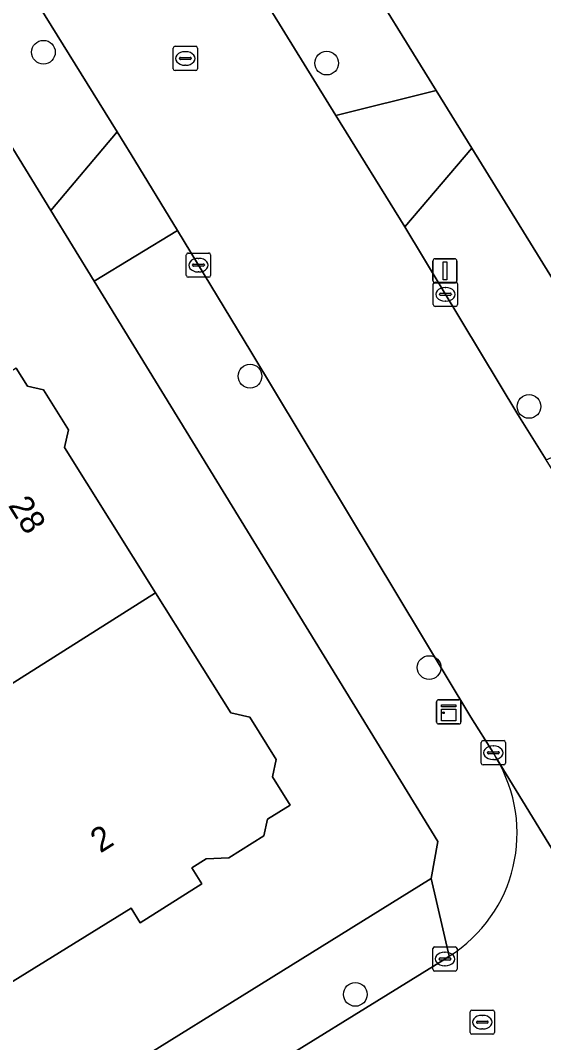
# Model space of a CAD drawing. Extents: x 161347 to 161881, y 382161 to 382804.
# Drawn here: x 161600.22 to 161621.78, y 382389.57 to 382431.67 of the extents above; entities that cross this region are included whole.
import ezdxf

# ---------------------------------------------------------------- set-up
doc = ezdxf.new("R2010")
doc.units = 0
for name, color, linetype in [('IMGEO_Boom', 7, 'Continuous'), ('IMGEO_Erf', 7, 'Continuous'), ('IMGEO_Kast', 7, 'Continuous'), ('IMGEO_Kolk', 7, 'Continuous'), ('IMGEO_Lichtmast', 7, 'Continuous'), ('IMGEO_Pand', 7, 'Continuous'), ('IMGEO_Pand_nummerreeks', 7, 'Continuous'), ('IMGEO_Rijbaan_lokaal_gesloten', 7, 'Continuous'), ('IMGEO_Rijbaan_lokaal_open', 7, 'Continuous'), ('IMGEO_Rioolput', 7, 'Continuous'), ('IMGEO_Voetpad_open', 7, 'Continuous')]:
    doc.layers.add(name, color=color, linetype=linetype)

msp = doc.modelspace()

# ---------------------------------------------------------------- linework, layer by layer
at = {"layer": 'IMGEO_Boom'}
for centre in [(161601.169, 382430.36), (161612.84, 382429.913), (161609.683, 382417.02), (161621.177, 382415.774), (161617.061, 382405.019), (161614.021, 382391.559)]:
    msp.add_circle(centre, 0.489, dxfattribs=at)
at = {"layer": 'IMGEO_Erf'}
for points in [[(161596.873, 382461.934), (161606.595, 382446.199), (161610.46, 382439.943), (161617.351, 382428.79), (161618.821, 382426.407), (161625.713, 382415.253), (161627.403, 382412.518), (161635.49, 382399.431), (161637.176, 382396.702), (161644.13, 382385.439), (161645.645, 382382.995), (161648.386, 382378.558), (161650.079, 382375.819), (161660.585, 382358.814), (161662.853, 382355.14), (161668.204, 382346.482), (161670.894, 382342.449), (161673.167, 382339.282), (161675.39, 382336.184)], [(161617.144, 382396.335), (161617.418, 382397.853), (161603.267, 382420.926), (161601.482, 382423.837), (161585.851, 382449.323), (161572.419, 382451.387), (161564.764, 382446.042), (161558.459, 382441.915), (161500, 382404.037), (161487.478, 382395.924)], [(161600.042, 382417.352), (161600.512, 382416.603), (161601.175, 382416.451), (161602.206, 382414.804), (161602.041, 382414.084), (161605.788, 382408.1), (161608.887, 382403.152), (161609.674, 382402.97), (161610.764, 382401.23), (161610.602, 382400.523), (161611.333, 382399.354), (161610.406, 382398.773), (161610.248, 382398.086), (161608.803, 382397.181), (161607.874, 382397.148), (161607.282, 382396.777), (161607.703, 382396.106), (161605.156, 382394.512), (161604.784, 382395.105), (161598.864, 382391.464)], [(161492.761, 382318.284), (161495.67, 382317.265), (161500, 382320.746), (161506.91, 382326.302), (161519.365, 382335.787), (161532.97, 382344.41), (161567.929, 382365.979), (161578.374, 382372.283), (161617.144, 382396.335)]]:
    msp.add_lwpolyline(points, dxfattribs=at)
at = {"layer": 'IMGEO_Kast'}
for p, q in [((161617.37, 382402.77), (161617.37, 382403.611)), ((161617.37, 382403.611), (161617.37, 382402.77)), ((161617.445, 382403.695), (161618.286, 382403.695)), ((161618.286, 382403.695), (161617.445, 382403.695)), ((161618.37, 382403.62), (161618.37, 382402.779)), ((161618.37, 382402.779), (161618.37, 382403.62)), ((161618.295, 382402.695), (161617.454, 382402.695)), ((161617.454, 382402.695), (161618.295, 382402.695))]:
    msp.add_line(p, q, dxfattribs=at)
for points in [[(161617.565, 382403.485), (161618.165, 382403.485), (161618.165, 382403.4), (161617.565, 382403.4), (161617.565, 382403.485)], [(161617.565, 382403.31), (161618.165, 382403.31), (161618.165, 382402.821), (161617.565, 382402.821), (161617.565, 382403.31)]]:
    msp.add_lwpolyline(points, dxfattribs=at)
msp.add_circle((161617.649, 382403.159), 0.0377, dxfattribs=at)
for centre, start, end in [((161617.448, 382403.617), 92.4484, 184.2845), ((161617.448, 382403.617), 92.4484, 184.2845), ((161618.292, 382403.617), 2.4484, 94.2845), ((161618.292, 382403.617), 2.4484, 94.2845), ((161617.448, 382402.773), 182.4484, 274.2845), ((161617.448, 382402.773), 182.4484, 274.2845), ((161618.292, 382402.773), 272.4484, 4.2845), ((161618.292, 382402.773), 272.4484, 4.2845)]:
    msp.add_arc(centre, 0.0779, start, end, dxfattribs=at)
at = {"layer": 'IMGEO_Kolk'}
for p, q in [((161607.133, 382422.092), (161607.985, 382422.092)), ((161607.058, 382421.166), (161607.058, 382422.018)), ((161607.546, 382421.872), (161607.571, 382421.872)), ((161608.059, 382422.018), (161608.059, 382421.166)), ((161607.317, 382421.586), (161607.317, 382421.598)), ((161607.755, 382421.549), (161607.357, 382421.549)), ((161607.36, 382421.635), (161607.758, 382421.635)), ((161607.569, 382421.312), (161607.544, 382421.312)), ((161607.801, 382421.598), (161607.801, 382421.586)), ((161607.985, 382421.092), (161607.133, 382421.092)), ((161617.234, 382419.965), (161617.234, 382420.817)), ((161617.309, 382420.891), (161618.161, 382420.891)), ((161618.235, 382420.817), (161618.235, 382419.965)), ((161617.493, 382420.385), (161617.493, 382420.397)), ((161617.536, 382420.434), (161617.934, 382420.434)), ((161617.722, 382420.671), (161617.747, 382420.671)), ((161617.977, 382420.397), (161617.977, 382420.385)), ((161617.931, 382420.348), (161617.533, 382420.348)), ((161617.745, 382420.111), (161617.72, 382420.111)), ((161618.161, 382419.891), (161617.309, 382419.891)), ((161619.207, 382401.083), (161619.207, 382401.935)), ((161619.282, 382402.009), (161620.134, 382402.009)), ((161620.208, 382401.935), (161620.208, 382401.083)), ((161619.466, 382401.503), (161619.466, 382401.515)), ((161619.904, 382401.466), (161619.506, 382401.466)), ((161619.509, 382401.552), (161619.907, 382401.552)), ((161619.695, 382401.789), (161619.72, 382401.789)), ((161619.95, 382401.515), (161619.95, 382401.503)), ((161619.718, 382401.229), (161619.693, 382401.229)), ((161620.134, 382401.009), (161619.282, 382401.009)), ((161617.213, 382392.591), (161617.213, 382393.443)), ((161617.288, 382393.517), (161618.14, 382393.517)), ((161618.214, 382393.443), (161618.214, 382392.591)), ((161617.472, 382393.011), (161617.472, 382393.023)), ((161617.515, 382393.06), (161617.913, 382393.06)), ((161617.701, 382393.297), (161617.726, 382393.297)), ((161617.956, 382393.023), (161617.956, 382393.011)), ((161617.91, 382392.974), (161617.512, 382392.974)), ((161617.724, 382392.737), (161617.699, 382392.737)), ((161618.14, 382392.517), (161617.288, 382392.517))]:
    msp.add_line(p, q, dxfattribs=at)
for points in [[(161607.133, 382422.092), (161607.985, 382422.092)], [(161607.058, 382421.166), (161607.058, 382422.018)], [(161608.059, 382422.018), (161608.059, 382421.166)], [(161607.985, 382421.092), (161607.133, 382421.092)], [(161617.234, 382419.965), (161617.234, 382420.817)], [(161617.309, 382420.891), (161618.161, 382420.891)], [(161618.235, 382420.817), (161618.235, 382419.965)], [(161618.161, 382419.891), (161617.309, 382419.891)], [(161619.207, 382401.083), (161619.207, 382401.935)], [(161619.282, 382402.009), (161620.134, 382402.009)], [(161620.208, 382401.935), (161620.208, 382401.083)], [(161620.134, 382401.009), (161619.282, 382401.009)], [(161617.213, 382392.591), (161617.213, 382393.443)], [(161617.288, 382393.517), (161618.14, 382393.517)], [(161618.214, 382393.443), (161618.214, 382392.591)], [(161618.14, 382392.517), (161617.288, 382392.517)]]:
    msp.add_lwpolyline(points, dxfattribs=at)
for centre, radius, start, end in [((161607.135, 382422.016), 0.0765, 91.552, 178.448), ((161607.135, 382422.016), 0.0765, 91.552, 178.448), ((161607.983, 382422.016), 0.0765, 1.552, 88.448), ((161607.983, 382422.016), 0.0765, 1.552, 88.448), ((161607.357, 382421.595), 0.0403, 85.8775, 175.7526), ((161607.354, 382421.585), 0.0366, 178.938, 274.7102), ((161607.758, 382421.592), 0.043, 264.8664, 352.4533), ((161607.762, 382421.597), 0.0386, 1.7309, 96.639), ((161607.135, 382421.168), 0.0765, 181.552, 268.448), ((161607.135, 382421.168), 0.0765, 181.552, 268.448), ((161607.983, 382421.168), 0.0765, 271.552, 358.448), ((161607.983, 382421.168), 0.0765, 271.552, 358.448), ((161617.311, 382420.815), 0.0765, 91.552, 178.448), ((161617.311, 382420.815), 0.0765, 91.552, 178.448), ((161618.159, 382420.815), 0.0765, 1.552, 88.448), ((161618.159, 382420.815), 0.0765, 1.552, 88.448), ((161617.533, 382420.394), 0.0403, 85.8775, 175.7526), ((161617.53, 382420.384), 0.0366, 178.938, 274.7102), ((161617.934, 382420.391), 0.043, 264.8664, 352.4533), ((161617.938, 382420.396), 0.0386, 1.7309, 96.639), ((161617.311, 382419.967), 0.0765, 181.552, 268.448), ((161617.311, 382419.967), 0.0765, 181.552, 268.448), ((161618.159, 382419.967), 0.0765, 271.552, 358.448), ((161618.159, 382419.967), 0.0765, 271.552, 358.448), ((161619.284, 382401.933), 0.0765, 91.552, 178.448), ((161619.284, 382401.933), 0.0765, 91.552, 178.448), ((161620.132, 382401.933), 0.0765, 1.552, 88.448), ((161620.132, 382401.933), 0.0765, 1.552, 88.448), ((161619.506, 382401.512), 0.0403, 85.8775, 175.7526), ((161619.503, 382401.502), 0.0366, 178.938, 274.7102), ((161619.907, 382401.509), 0.043, 264.8664, 352.4533), ((161619.911, 382401.514), 0.0386, 1.7309, 96.639), ((161619.284, 382401.085), 0.0765, 181.552, 268.448), ((161619.284, 382401.085), 0.0765, 181.552, 268.448), ((161620.132, 382401.085), 0.0765, 271.552, 358.448), ((161620.132, 382401.085), 0.0765, 271.552, 358.448), ((161617.29, 382393.441), 0.0765, 91.552, 178.448), ((161617.29, 382393.441), 0.0765, 91.552, 178.448), ((161618.138, 382393.441), 0.0765, 1.552, 88.448), ((161618.138, 382393.441), 0.0765, 1.552, 88.448), ((161617.512, 382393.02), 0.0403, 85.8775, 175.7526), ((161617.917, 382393.022), 0.0386, 1.7309, 96.639), ((161617.509, 382393.01), 0.0366, 178.938, 274.7102), ((161617.913, 382393.017), 0.043, 264.8664, 352.4533), ((161617.29, 382392.593), 0.0765, 181.552, 268.448), ((161617.29, 382392.593), 0.0765, 181.552, 268.448), ((161618.138, 382392.593), 0.0765, 271.552, 358.448), ((161618.138, 382392.593), 0.0765, 271.552, 358.448)]:
    msp.add_arc(centre, radius, start, end, dxfattribs=at)
for centre, major_axis, ratio, start_param, end_param in [((161607.545, 382421.592), (-0.387, 0.002), 0.722429, 4.712389, 7.853982), ((161607.57, 382421.592), (-0.39, 0.002), 0.717154, 1.570796, 4.712389), ((161617.721, 382420.391), (-0.387, 0.002), 0.722429, 4.712389, 7.853982), ((161617.746, 382420.391), (-0.39, 0.002), 0.717154, 1.570796, 4.712389), ((161619.694, 382401.509), (-0.387, 0.002), 0.722429, 4.712389, 7.853982), ((161619.719, 382401.509), (-0.39, 0.002), 0.717154, 1.570796, 4.712389), ((161617.7, 382393.017), (-0.387, 0.002), 0.722429, 4.712389, 7.853982), ((161617.725, 382393.017), (-0.39, 0.002), 0.717154, 1.570796, 4.712389)]:
    msp.add_ellipse(centre, major_axis=major_axis, ratio=ratio, start_param=start_param, end_param=end_param, dxfattribs=at)
at = {"layer": 'IMGEO_Lichtmast'}
for p, q in [((161617.216, 382420.958), (161617.216, 382421.758)), ((161617.216, 382421.758), (161617.216, 382420.958)), ((161617.316, 382421.858), (161618.106, 382421.858)), ((161618.106, 382421.858), (161617.316, 382421.858)), ((161618.206, 382421.758), (161618.206, 382420.958)), ((161618.206, 382420.958), (161618.206, 382421.758)), ((161618.106, 382420.858), (161617.316, 382420.858)), ((161617.316, 382420.858), (161618.106, 382420.858))]:
    msp.add_line(p, q, dxfattribs=at)
msp.add_lwpolyline([(161617.636, 382421.733), (161617.786, 382421.733), (161617.786, 382420.983), (161617.636, 382420.983), (161617.636, 382421.733)], dxfattribs=at)
for centre, start, end in [((161617.316, 382421.758), 90, 180), ((161617.316, 382421.758), 90, 180), ((161618.106, 382421.758), 0, 90), ((161618.106, 382421.758), 360, 90), ((161617.316, 382420.958), 180, 270), ((161617.316, 382420.958), 180, 270), ((161618.106, 382420.958), 270, 0), ((161618.106, 382420.958), 270, 0)]:
    msp.add_arc(centre, 0.1, start, end, dxfattribs=at)
at = {"layer": 'IMGEO_Pand'}
for points in [[(161605.788, 382408.1), (161602.041, 382414.084), (161602.206, 382414.804), (161601.175, 382416.451), (161600.512, 382416.603), (161600.042, 382417.352), (161596.458, 382415.108), (161595.867, 382416.051), (161592.936, 382414.216), (161593.475, 382413.355), (161590.899, 382411.741), (161587.516, 382417.205), (161582.631, 382414.18), (161588.174, 382405.232), (161589.273, 382405.913), (161592.949, 382399.977)], [(161605.788, 382408.1), (161592.949, 382399.977), (161591.067, 382398.82), (161593.254, 382395.293), (161593.788, 382394.431), (161596.11, 382395.885), (161598.864, 382391.464), (161604.784, 382395.105), (161605.156, 382394.512), (161607.703, 382396.106), (161607.282, 382396.777), (161607.874, 382397.148), (161608.803, 382397.181), (161610.248, 382398.086), (161610.406, 382398.773), (161611.333, 382399.354), (161610.602, 382400.523), (161610.764, 382401.23), (161609.674, 382402.97), (161608.887, 382403.152)]]:
    msp.add_lwpolyline(points, close=True, dxfattribs=at)
at = {"layer": 'IMGEO_Rijbaan_lokaal_gesloten'}
for points in [[(161639.764, 382384.664), (161633.924, 382394.091), (161633.068, 382395.474), (161631.747, 382397.625), (161626.54, 382406.102), (161624.099, 382410.02), (161621.888, 382413.569), (161620.72, 382415.443), (161616.056, 382423.173), (161613.224, 382427.758), (161610.209, 382432.64), (161607.182, 382437.357), (161606.889, 382437.813), (161602.942, 382444.409), (161602.826, 382444.603), (161598.247, 382451.88)], [(161597.797, 382437.287), (161600.498, 382433.066), (161604.206, 382427.087), (161604.791, 382426.143), (161606.697, 382423.012), (161609.721, 382418.042), (161618.786, 382402.977), (161619.705, 382401.516), (161619.82, 382401.3), (161628.81, 382386.642), (161629.805, 382385.029), (161636.066, 382375.288), (161638.138, 382371.942), (161640.246, 382368.539), (161641.764, 382366.087), (161644.02, 382362.47), (161646.027, 382359.252), (161648.102, 382355.925), (161653.812, 382346.627), (161657.705, 382340.384), (161659.046, 382338.226)]]:
    msp.add_lwpolyline(points, dxfattribs=at)
at = {"layer": 'IMGEO_Rijbaan_lokaal_open'}
for points in [[(161628.81, 382386.642), (161619.82, 382401.3)], [(161617.891, 382393.131), (161617.711, 382393.014), (161608.544, 382387.356), (161611.66, 382382.307), (161620.649, 382387.867), (161620.875, 382387.995)]]:
    msp.add_lwpolyline(points, dxfattribs=at)
msp.add_arc((161614.697, 382398.197), 5.989, 302.2259, 31.2016, dxfattribs=at)
at = {"layer": 'IMGEO_Rioolput'}
for p, q in [((161606.517, 382429.678), (161606.517, 382430.53)), ((161606.592, 382430.604), (161607.444, 382430.604)), ((161607.518, 382430.53), (161607.518, 382429.678)), ((161606.776, 382430.098), (161606.776, 382430.11)), ((161607.214, 382430.061), (161606.816, 382430.061)), ((161606.819, 382430.147), (161607.217, 382430.147)), ((161607.005, 382430.384), (161607.03, 382430.384)), ((161607.26, 382430.11), (161607.26, 382430.098)), ((161607.028, 382429.824), (161607.003, 382429.824)), ((161607.444, 382429.604), (161606.592, 382429.604)), ((161618.828, 382390.914), (161619.68, 382390.914)), ((161618.753, 382389.988), (161618.753, 382390.84)), ((161619.241, 382390.694), (161619.266, 382390.694)), ((161619.754, 382390.84), (161619.754, 382389.988)), ((161619.012, 382390.408), (161619.012, 382390.42)), ((161619.45, 382390.371), (161619.052, 382390.371)), ((161619.055, 382390.457), (161619.453, 382390.457)), ((161619.264, 382390.134), (161619.239, 382390.134)), ((161619.496, 382390.42), (161619.496, 382390.408)), ((161619.68, 382389.914), (161618.828, 382389.914))]:
    msp.add_line(p, q, dxfattribs=at)
for points in [[(161606.517, 382429.678), (161606.517, 382430.53)], [(161606.592, 382430.604), (161607.444, 382430.604)], [(161607.518, 382430.53), (161607.518, 382429.678)], [(161607.444, 382429.604), (161606.592, 382429.604)], [(161618.828, 382390.914), (161619.68, 382390.914)], [(161618.753, 382389.988), (161618.753, 382390.84)], [(161619.754, 382390.84), (161619.754, 382389.988)], [(161619.68, 382389.914), (161618.828, 382389.914)]]:
    msp.add_lwpolyline(points, dxfattribs=at)
for centre, radius, start, end in [((161606.594, 382430.528), 0.0765, 91.552, 178.448), ((161606.594, 382430.528), 0.0765, 91.552, 178.448), ((161607.442, 382430.528), 0.0765, 1.552, 88.448), ((161607.442, 382430.528), 0.0765, 1.552, 88.448), ((161606.816, 382430.107), 0.0403, 85.8775, 175.7526), ((161606.813, 382430.097), 0.0366, 178.938, 274.7102), ((161607.217, 382430.104), 0.043, 264.8664, 352.4533), ((161607.221, 382430.109), 0.0386, 1.7309, 96.639), ((161606.594, 382429.68), 0.0765, 181.552, 268.448), ((161606.594, 382429.68), 0.0765, 181.552, 268.448), ((161607.442, 382429.68), 0.0765, 271.552, 358.448), ((161607.442, 382429.68), 0.0765, 271.552, 358.448), ((161618.83, 382390.838), 0.0765, 91.552, 178.448), ((161618.83, 382390.838), 0.0765, 91.552, 178.448), ((161619.678, 382390.838), 0.0765, 1.552, 88.448), ((161619.678, 382390.838), 0.0765, 1.552, 88.448), ((161619.052, 382390.417), 0.0403, 85.8775, 175.7526), ((161619.049, 382390.407), 0.0366, 178.938, 274.7102), ((161619.453, 382390.414), 0.043, 264.8664, 352.4533), ((161619.457, 382390.419), 0.0386, 1.7309, 96.639), ((161618.83, 382389.99), 0.0765, 181.552, 268.448), ((161618.83, 382389.99), 0.0765, 181.552, 268.448), ((161619.678, 382389.99), 0.0765, 271.552, 358.448), ((161619.678, 382389.99), 0.0765, 271.552, 358.448)]:
    msp.add_arc(centre, radius, start, end, dxfattribs=at)
for centre, major_axis, ratio, start_param, end_param in [((161607.004, 382430.104), (-0.387, 0.002), 0.722429, 4.712389, 7.853982), ((161607.029, 382430.104), (-0.39, 0.002), 0.717154, 1.570796, 4.712389), ((161619.24, 382390.414), (-0.387, 0.002), 0.722429, 4.712389, 7.853982), ((161619.265, 382390.414), (-0.39, 0.002), 0.717154, 1.570796, 4.712389)]:
    msp.add_ellipse(centre, major_axis=major_axis, ratio=ratio, start_param=start_param, end_param=end_param, dxfattribs=at)
at = {"layer": 'IMGEO_Voetpad_open'}
for points in [[(161575.352, 382455.965), (161571.268, 382453.342), (161572.419, 382451.387), (161585.851, 382449.323), (161601.482, 382423.837), (161604.206, 382427.087), (161600.498, 382433.066), (161597.797, 382437.287), (161597.375, 382437.02), (161592.751, 382444.36), (161593.173, 382444.627), (161590.887, 382448.303)], [(161619.82, 382401.3), (161619.705, 382401.516), (161618.786, 382402.977), (161609.721, 382418.042), (161606.697, 382423.012), (161603.267, 382420.926), (161617.418, 382397.853), (161617.144, 382396.335), (161617.891, 382393.131)], [(161588.821, 382375.192), (161595.489, 382379.316), (161598.349, 382381.063), (161606.195, 382385.906), (161608.544, 382387.356), (161617.711, 382393.014), (161617.891, 382393.131), (161617.144, 382396.335), (161578.374, 382372.283), (161567.929, 382365.979), (161532.97, 382344.41), (161519.365, 382335.787), (161506.91, 382326.302), (161500, 382320.746), (161495.67, 382317.265), (161490.849, 382315.425), (161491.37, 382314.562)]]:
    msp.add_lwpolyline(points, dxfattribs=at)
for points in [[(161607.182, 382437.357), (161610.209, 382432.64), (161613.224, 382427.758), (161617.351, 382428.79), (161610.46, 382439.943)], [(161613.224, 382427.758), (161616.056, 382423.173), (161618.821, 382426.407), (161617.351, 382428.79)], [(161606.697, 382423.012), (161604.791, 382426.143), (161604.206, 382427.087), (161601.482, 382423.837), (161603.267, 382420.926)], [(161618.821, 382426.407), (161616.056, 382423.173), (161620.72, 382415.443), (161621.888, 382413.569), (161625.713, 382415.253)]]:
    msp.add_lwpolyline(points, close=True, dxfattribs=at)
msp.add_arc((161614.697, 382398.197), 5.989, 302.2259, 31.2016, dxfattribs=at)

# ---------------------------------------------------------------- texts
at = {"layer": 'IMGEO_Pand_nummerreeks'}
for s, rotation, p in [('28', 301.8443, (161599.695, 382411.695)), ('2', 32.0517, (161603.515, 382397.356))]:
    msp.add_text(s, height=1, rotation=rotation, dxfattribs=at).set_placement(p)

doc.saveas('drawing.dxf')
